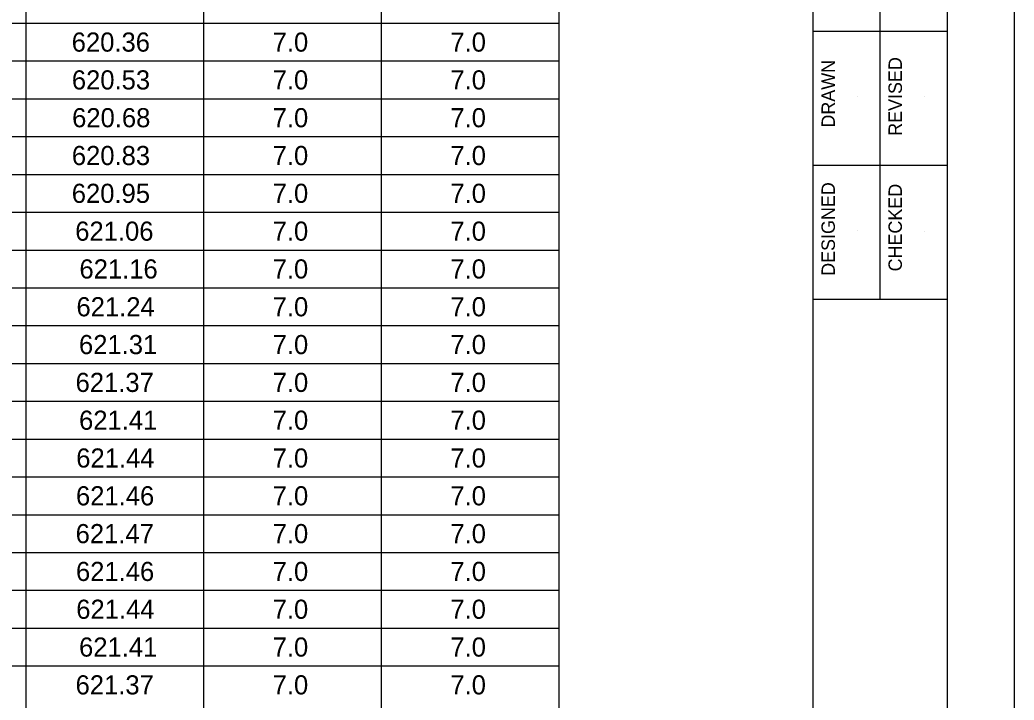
# Model space of a CAD drawing. Extents: x -0.2 to 33.8, y -0.1 to 21.9.
# Drawn here: x 26.36 to 33.78, y 10.88 to 15.95 of the extents above; entities that cross this region are included whole.
import ezdxf

# ---------------------------------------------------------------- set-up
doc = ezdxf.new("R2010")
doc.units = 0
for name, color, linetype in [('BR_P_Gen_Text', 7, 'Continuous'), ('SH_Border', 7, 'Continuous'), ('SH_Cut_Line', 7, 'Continuous'), ('SH_Data', 7, 'Continuous')]:
    doc.layers.add(name, color=color, linetype=linetype)

msp = doc.modelspace()

# ---------------------------------------------------------------- linework, layer by layer
at = {"layer": 'BR_P_Gen_Text'}
for p, q in [((30.3786, 19.8361), (30.3786, 2.6673)), ((26.4003, 19.554), (26.4003, 2.9494)), ((27.7264, 19.554), (27.7264, 2.9494)), ((29.0525, 19.554), (29.0525, 2.6673)), ((17.7383, 15.9283), (30.3786, 15.9283)), ((17.7383, 15.6462), (30.3786, 15.6462)), ((17.7383, 15.364), (30.3786, 15.364)), ((17.7383, 15.0819), (30.3786, 15.0819)), ((17.7383, 14.7997), (30.3786, 14.7997)), ((17.7383, 14.5176), (30.3786, 14.5176)), ((17.7383, 14.2354), (30.3786, 14.2354)), ((17.7383, 13.9533), (30.3786, 13.9533)), ((17.7383, 13.6711), (30.3786, 13.6711)), ((17.7383, 13.389), (30.3786, 13.389)), ((17.7383, 13.1068), (30.3786, 13.1068)), ((17.7383, 12.8247), (30.3786, 12.8247)), ((17.7383, 12.5425), (30.3786, 12.5425)), ((17.7383, 12.2604), (30.3786, 12.2604)), ((17.7383, 11.9782), (30.3786, 11.9782)), ((17.7383, 11.6961), (30.3786, 11.6961)), ((17.7383, 11.4139), (30.3786, 11.4139)), ((17.7383, 11.1318), (30.3786, 11.1318))]:
    msp.add_line(p, q, dxfattribs=at)
at = {"layer": 'SH_Border'}
for p, q in [((32.2753, 0.368), (32.2753, 21.368)), ((32.7753, 13.8681), (32.7753, 17.8681)), ((32.2753, 15.8681), (33.2753, 15.8681)), ((32.2753, 14.8681), (33.2753, 14.8681)), ((32.2753, 13.8681), (33.2753, 13.8681))]:
    msp.add_line(p, q, dxfattribs=at)
msp.add_lwpolyline([(1.7753, 21.368), (33.2753, 21.368), (33.2753, 0.368), (1.7753, 0.368)], close=True, dxfattribs=at)
at = {"layer": 'SH_Cut_Line'}
msp.add_lwpolyline([(-0.2247, 21.868), (33.7753, 21.868), (33.7753, -0.132), (-0.2247, -0.132)], close=True, dxfattribs=at)
at = {"layer": 'SH_Data'}
for p, q in [((32.6086, 15.3779), (32.6086, 15.3779)), ((33.1086, 15.3779), (33.1086, 15.3779)), ((32.6086, 14.3779), (32.6086, 14.3779)), ((33.1086, 14.377), (33.1086, 14.377))]:
    msp.add_line(p, q, dxfattribs=at)

# ---------------------------------------------------------------- texts
at = {"layer": 'BR_P_Gen_Text'}
for s, p in [('620.36', (26.7426, 15.7159)), ('7.0', (28.2422, 15.7159)), ('7.0', (29.5683, 15.7159)), ('620.53', (26.7436, 15.4337)), ('7.0', (28.2422, 15.4337)), ('7.0', (29.5683, 15.4337)), ('620.68', (26.7456, 15.1516)), ('7.0', (28.2422, 15.1516)), ('7.0', (29.5683, 15.1516)), ('620.83', (26.7436, 14.8694)), ('7.0', (28.2422, 14.8694)), ('7.0', (29.5683, 14.8694)), ('620.95', (26.7431, 14.5873)), ('7.0', (28.2422, 14.5873)), ('7.0', (29.5683, 14.5873)), ('621.06', (26.7689, 14.3051)), ('7.0', (28.2422, 14.3051)), ('7.0', (29.5683, 14.3051)), ('621.16', (26.8003, 14.023)), ('7.0', (28.2422, 14.023)), ('7.0', (29.5683, 14.023)), ('621.24', (26.7781, 13.7408)), ('7.0', (28.2422, 13.7408)), ('7.0', (29.5683, 13.7408)), ('621.31', (26.7969, 13.4587)), ('7.0', (28.2422, 13.4587)), ('7.0', (29.5683, 13.4587)), ('621.37', (26.7715, 13.1765)), ('7.0', (28.2422, 13.1765)), ('7.0', (29.5683, 13.1765)), ('621.41', (26.7974, 12.8944)), ('7.0', (28.2422, 12.8944)), ('7.0', (29.5683, 12.8944)), ('621.44', (26.7765, 12.6122)), ('7.0', (28.2422, 12.6122)), ('7.0', (29.5683, 12.6122)), ('621.46', (26.7745, 12.3301)), ('7.0', (28.2422, 12.3301)), ('7.0', (29.5683, 12.3301)), ('621.47', (26.772, 12.0479)), ('7.0', (28.2422, 12.0479)), ('7.0', (29.5683, 12.0479)), ('621.46', (26.7745, 11.7658)), ('7.0', (28.2422, 11.7658)), ('7.0', (29.5683, 11.7658)), ('621.44', (26.7765, 11.4836)), ('7.0', (28.2422, 11.4836)), ('7.0', (29.5683, 11.4836)), ('621.41', (26.7974, 11.2015)), ('7.0', (28.2422, 11.2015)), ('7.0', (29.5683, 11.2015)), ('621.37', (26.7715, 10.9193)), ('7.0', (28.2422, 10.9193)), ('7.0', (29.5683, 10.9193))]:
    msp.add_text(s, height=0.14277, dxfattribs=at).set_placement(p)
at = {"layer": 'SH_Data'}
for s, p in [('REVISED', (32.9378, 15.0878)), ('DRAWN', (32.4378, 15.1492)), ('DESIGNED', (32.4378, 14.0429)), ('CHECKED', (32.9378, 14.0759))]:
    msp.add_text(s, height=0.1, rotation=90, dxfattribs=at).set_placement(p)

doc.saveas('drawing.dxf')
